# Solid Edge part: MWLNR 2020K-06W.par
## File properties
Author: LABUSIG
Template: iso metric part.par
Last saved by: LABUSIG
Revision: 1
Application: Solid Edge
Accuracy: 0.990
Username: LABUSIG
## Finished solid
Body 1: solid body, 267 faces, 752 edges, 487 vertices.
  Faces by surface: spline 163, cylinder 68, plane 36
  Edges by curve: curve on surface 370, spline 291, line 84, circle 7
Body 2: solid body, 125 faces, 329 edges, 209 vertices.
  Faces by surface: plane 54, cylinder 27, torus 24, cone 14, spline 6
  Edges by curve: line 148, circle 68, spline 57, curve on surface 56
Bounding box of the edges (mm; curved faces can reach further): 24.999 x 27.000 x 124.999, from (-24.9988, 0, -124.9988) to (0, 27, 0).
Cylindrical faces by radius (mm): R0.5357 x3, R0.7 x6, R0.8 x7, R1.5 x9, R1.504 x3, R1.905 x4, R1.9266 x1, R1.9315 x1, R1.9325 x1, R2 x1, R2.0617 x1, R2.0724 x2, R2.19 x2, R2.2008 x1, R2.3524 x2, R2.3638 x1, R2.45 x2, R2.5 x2, R3.1432 x1, R3.1464 x2, R3.1472 x1, R3.2318 x1, R3.2376 x1, R3.2377 x1, R3.2949 x1, R3.417 x1, R3.4171 x1, R3.4498 x1, R3.4617 x2, R4 x2, R6.072 x3, R6.1045 x1, R6.1656 x2, R6.5 x1, R7.0261 x2, R7.0262 x1, R7.1002 x3, R7.6649 x1, R7.8369 x2, R12.6967 x2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
Conical faces (half-angle, radius in mm at the cone's reference point): 1.9092 deg R2.45 x3, 9 deg R5.0185 x2, 15 deg R3.2045 x1, 15 deg R15.2045 x2, 15 deg R16.1551 x2, 60.5 deg R2.653 x2, 75 deg R2.5 x2
Toroidal faces (ring radius, tube radius in mm): R0.5482 r5 x1, R3.4977 r1.5 x1, R3.4988 r1.5 x1, R4.526 r0.7 x1, R5.4643 r0.3 x1, R6.5 r1.5 x1, R7.2427 r3 x1, R8.4518 r6.5 x2, R12.0482 r6.5 x1, R12.5482 r5 x2, R13.2573 r3 x2, R15.0357 r0.3 x2, R17.4643 r0.3 x2, R19.2427 r3 x2, R19.9518 r5 x2, R24.0482 r6.5 x2
Planar faces by outward normal: +x 1, +y 2, +z 1, -x 1, -y 1, oblique 84
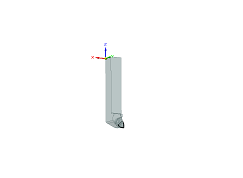
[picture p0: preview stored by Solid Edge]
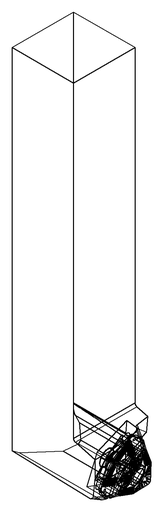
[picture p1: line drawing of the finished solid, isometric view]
